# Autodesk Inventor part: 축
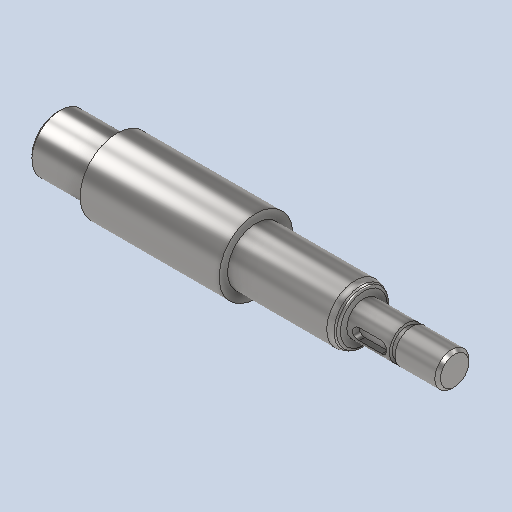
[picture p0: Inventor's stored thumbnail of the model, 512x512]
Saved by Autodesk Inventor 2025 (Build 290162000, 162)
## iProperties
Created: 2024-08
Part Number: 축
Material: 강철, 연강
Document SubType Name: Modeling
Designer: samsung
Density: 7.86 g/cm^3
Appearance: 기본값
Author: jhkim
Sending System: Autodesk Inventor 2025
Preprocessor: ST-DEVELOPER v20
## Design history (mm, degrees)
feature "솔리드2"
node "솔리드1"
